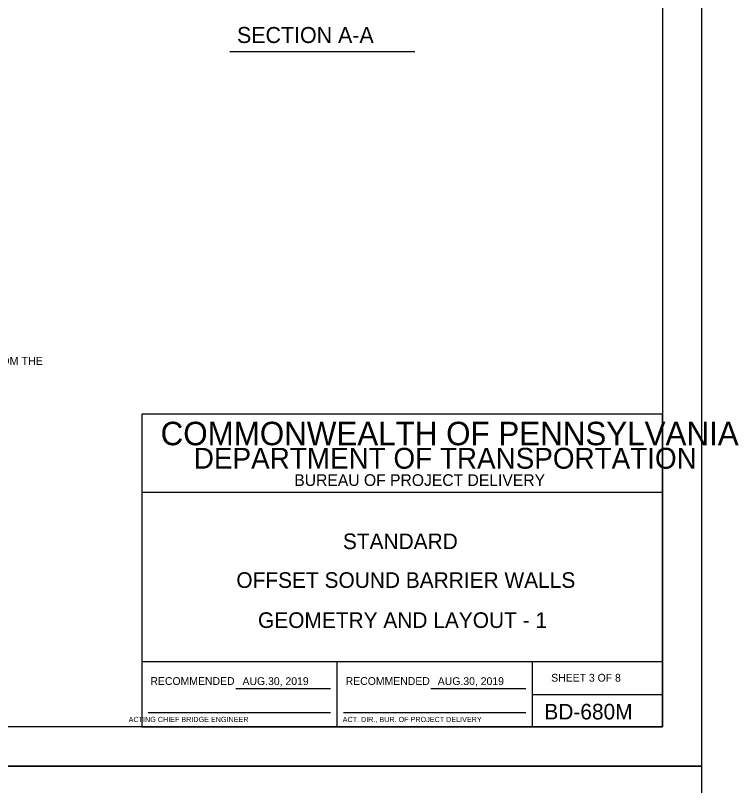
# Model space of a CAD drawing. Extents: x 3385 to 6532, y -616 to 1166.
# Drawn here: x 6020.8 to 6298.6, y 564.2 to 859.8 of the extents above; entities that cross this region are included whole.
import ezdxf

# ---------------------------------------------------------------- set-up
doc = ezdxf.new("R2010")
doc.units = 0
for name, color, linetype in [('1', 7, 'Continuous'), ('2', 7, 'Continuous'), ('PLT-BNDY', 7, 'Continuous')]:
    doc.layers.add(name, color=color, linetype=linetype)

msp = doc.modelspace()

# ---------------------------------------------------------------- linework, layer by layer
at = {"layer": '1'}
for p, q in [((6103.11, 845.95), (6174.23, 845.95)), ((6144.34, 586.69), (6144.34, 611.69)), ((6105.43, 601.41), (6141.84, 601.41)), ((6180.43, 601.41), (6216.84, 601.41)), ((6071.84, 592.19), (6141.84, 592.19)), ((6146.84, 592.19), (6216.84, 592.19))]:
    msp.add_line(p, q, dxfattribs=at)
at = {"layer": '2'}
for p, q in [((6269.34, 1150.69), (6269.34, 586.69)), ((6269.34, 706.69), (6069.34, 706.69)), ((6069.34, 706.69), (6069.34, 586.69)), ((6269.34, 586.69), (6269.34, 706.69)), ((6269.34, 676.69), (6069.34, 676.69)), ((6269.34, 611.69), (6069.34, 611.69)), ((6219.34, 611.69), (6219.34, 586.69)), ((6219.34, 599.19), (6269.34, 599.19)), ((6269.34, 586.69), (5483.34, 586.69)), ((6069.34, 586.69), (6269.34, 586.69))]:
    msp.add_line(p, q, dxfattribs=at)
at = {"layer": 'PLT-BNDY'}
for points in [[(5443.34, 1165.69), (6284.34, 1165.69), (6284.34, 571.69), (5443.34, 571.69)], [(5443.34, 571.69), (6284.34, 571.69), (6284.34, -22.31), (5443.34, -22.31)]]:
    msp.add_lwpolyline(points, close=True, dxfattribs=at)

# ---------------------------------------------------------------- texts
at = {"layer": '1'}
for s, height, p in [('SECTION A-A', 6.144, (6105.93, 849.19)), ('GRADE GROUND TO DRAIN WATER AWAY FROM THE', 3.072, (5924.77, 725.64)), ('STANDARD', 6, (6146.59, 654.94)), ('OFFSET SOUND BARRIER WALLS', 6.0001, (6105.67, 640.07)), ('GEOMETRY AND LAYOUT - 1', 6.0001, (6113.99, 624.69)), ('SHEET 3 OF 8', 3, (6226.59, 604.08)), ('RECOMMENDED', 3, (6072.67, 602.82)), ('AUG.30, 2019', 3, (6108.03, 602.78)), ('RECOMMENDED', 3, (6147.67, 602.82)), ('AUG.30, 2019', 3, (6183.03, 602.78)), ('BD-680M', 6, (6223.97, 589.57)), ('       ACTING CHIEF BRIDGE ENGINEER', 2.0002, (6058.93, 588.57)), ('ACT. DIR., BUR. OF PROJECT DELIVERY', 2.0002, (6146.5, 588.57))]:
    msp.add_text(s, height=height, dxfattribs=at).set_placement(p)
at = {"layer": '2'}
for s, height, p in [('COMMONWEALTH OF PENNSYLVANIA', 9, (6076.59, 694.82)), ('DEPARTMENT OF TRANSPORTATION', 8.0002, (6089.34, 685.82)), ('BUREAU OF PROJECT DELIVERY', 4.5, (6127.93, 679.19))]:
    msp.add_text(s, height=height, dxfattribs=at).set_placement(p)

doc.saveas('drawing.dxf')
